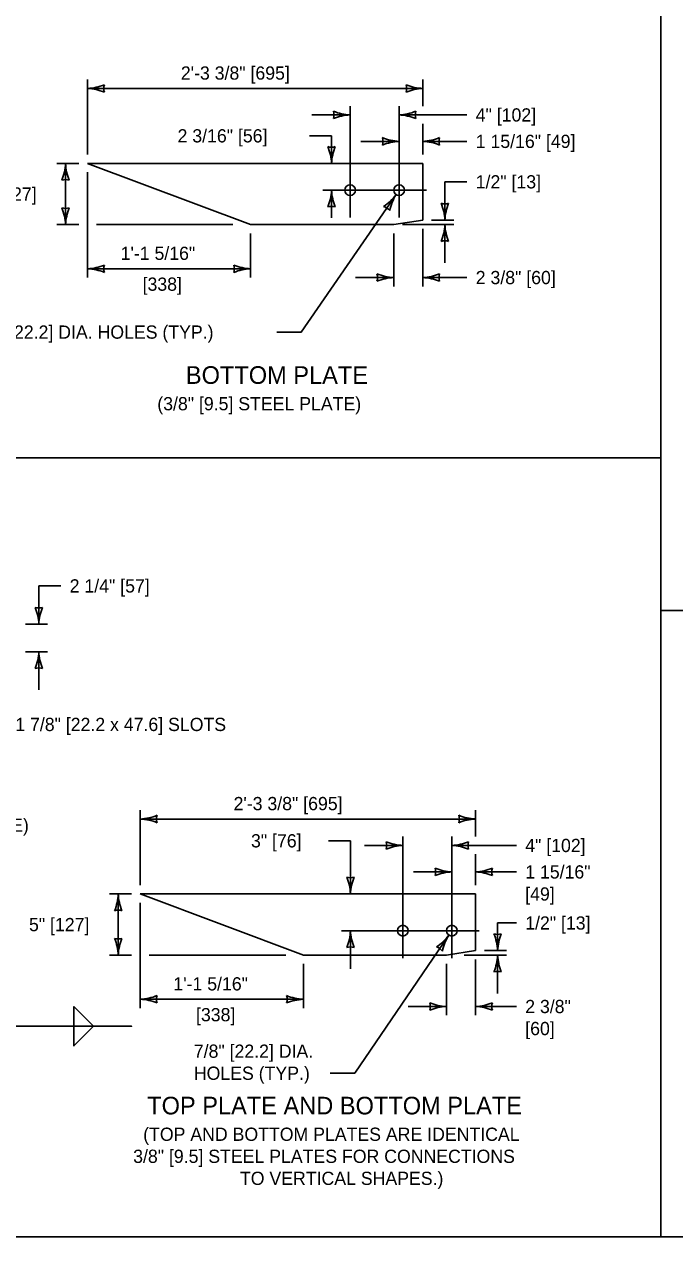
# Model space of a CAD drawing. Extents: x 49991.4 to 50021, y 49987.6 to 50011.4.
# Drawn here: x 50003.04 to 50005.99, y 49987.8 to 49993.3 of the extents above; entities that cross this region are included whole.
import ezdxf

# ---------------------------------------------------------------- set-up
doc = ezdxf.new("R2010")
doc.units = 0
for name, color, linetype in [('Level 1', 7, 'Continuous'), ('Level 2', 7, 'Continuous'), ('Level 3', 7, 'Continuous'), ('Level 5', 7, 'Continuous'), ('Level 7', 7, 'Continuous')]:
    doc.layers.add(name, color=color, linetype=linetype)

msp = doc.modelspace()

# ---------------------------------------------------------------- linework, layer by layer
at = {"layer": 'Level 1'}
for p, q in [((50005.9232, 49998.9992), (50005.9232, 49987.7988)), ((50004.8437, 49992.6677), (50003.3229, 49992.6677)), ((50003.3229, 49992.6677), (50004.0625, 49992.39)), ((50004.8437, 49992.6677), (50004.8437, 49992.4108)), ((50004.7118, 49992.39), (50004.0625, 49992.39)), ((50004.8437, 49992.4108), (50004.7118, 49992.39)), ((50005.9232, 49991.3327), (49999.3835, 49991.3327)), ((50005.9232, 49990.6395), (50016.7501, 49990.6395)), ((50005.083, 49989.3538), (50003.5621, 49989.3538)), ((50003.5621, 49989.3538), (50004.3017, 49989.0761)), ((50005.083, 49989.3538), (50005.083, 49989.0969)), ((50004.951, 49989.0761), (50004.3017, 49989.0761)), ((50005.083, 49989.0969), (50004.951, 49989.0761))]:
    msp.add_line(p, q, dxfattribs=at)
msp.add_lwpolyline([(49999.3835, 49998.9992), (50016.7501, 49998.9992), (50016.7501, 49987.7988), (49999.3835, 49987.7988)], close=True, dxfattribs=at)
for centre in [(50004.5138, 49992.5462), (50004.7361, 49992.5462), (50004.7531, 49989.1872), (50004.9753, 49989.1872)]:
    msp.add_circle(centre, 0.0243, dxfattribs=at)
at = {"layer": 'Level 3'}
for p, q in [((50003.3229, 49992.7077), (50003.3229, 49993.0477)), ((50004.8437, 49992.9277), (50004.8437, 49993.0477)), ((50004.8437, 49993.0077), (50003.3229, 49993.0077)), ((50004.5138, 49992.8877), (50004.3404, 49992.8877)), ((50005.0437, 49992.8877), (50004.7361, 49992.8877)), ((50004.8437, 49992.7077), (50004.8437, 49992.8477)), ((50004.4295, 49992.7929), (50004.3295, 49992.7929)), ((50004.4295, 49992.6677), (50004.4295, 49992.7929)), ((50004.7361, 49992.7677), (50004.5626, 49992.7677)), ((50005.0437, 49992.7677), (50004.8437, 49992.7677)), ((50003.2829, 49992.6677), (50003.1829, 49992.6677)), ((50003.2229, 49992.6677), (50003.2229, 49992.39)), ((50003.3229, 49992.6277), (50003.3229, 49992.15)), ((50004.9437, 49992.4108), (50004.9437, 49992.5842)), ((50004.9437, 49992.5842), (50005.0437, 49992.5842)), ((50004.4295, 49992.5462), (50004.4295, 49992.421)), ((50003.2829, 49992.39), (50003.1829, 49992.39)), ((50003.9825, 49992.39), (50003.3629, 49992.39)), ((50004.7518, 49992.39), (50004.9837, 49992.39)), ((50004.8437, 49992.3708), (50004.8437, 49992.11)), ((50004.8837, 49992.4108), (50004.9837, 49992.4108)), ((50004.9437, 49992.39), (50004.9437, 49992.2165)), ((50004.0625, 49992.35), (50004.0625, 49992.15)), ((50004.7118, 49992.35), (50004.7118, 49992.11)), ((50004.0625, 49992.19), (50003.3229, 49992.19)), ((50004.7118, 49992.15), (50004.5383, 49992.15)), ((50005.0437, 49992.15), (50004.8437, 49992.15)), ((50003.1017, 49990.5778), (50003.1017, 49990.7512)), ((50003.1017, 49990.7512), (50003.2017, 49990.7512)), ((50003.0418, 49990.5778), (50003.1417, 49990.5778)), ((50003.0418, 49990.4528), (50003.1417, 49990.4528)), ((50003.1017, 49990.2794), (50003.1017, 49990.4528)), ((50003.5621, 49989.3938), (50003.5621, 49989.7338)), ((50005.083, 49989.6138), (50005.083, 49989.7338)), ((50005.083, 49989.6938), (50003.5621, 49989.6938)), ((50004.5154, 49989.5949), (50004.4154, 49989.5949)), ((50004.5154, 49989.3538), (50004.5154, 49989.5949)), ((50004.7531, 49989.5738), (50004.5797, 49989.5738)), ((50005.2682, 49989.5738), (50004.9753, 49989.5738)), ((50005.083, 49989.3938), (50005.083, 49989.5338)), ((50004.9753, 49989.4538), (50004.8019, 49989.4538)), ((50005.2682, 49989.4538), (50005.083, 49989.4538)), ((50003.5221, 49989.3538), (50003.4221, 49989.3538)), ((50003.4621, 49989.3538), (50003.4621, 49989.0761)), ((50003.5621, 49989.3138), (50003.5621, 49988.8361)), ((50005.183, 49989.0969), (50005.183, 49989.2221)), ((50005.183, 49989.2221), (50005.2682, 49989.2221)), ((50003.5221, 49989.0761), (50003.4221, 49989.0761)), ((50004.2217, 49989.0761), (50003.6021, 49989.0761)), ((50005.031, 49989.0761), (50005.223, 49989.0761)), ((50005.123, 49989.0969), (50005.223, 49989.0969)), ((50005.183, 49989.0761), (50005.183, 49988.9026)), ((50004.3017, 49989.0361), (50004.3017, 49988.8361)), ((50004.951, 49989.0361), (50004.951, 49988.8033)), ((50005.083, 49989.0569), (50005.083, 49988.8033)), ((50004.3017, 49988.8761), (50003.5621, 49988.8761)), ((50004.951, 49988.8433), (50004.7776, 49988.8433)), ((50005.2682, 49988.8433), (50005.083, 49988.8433))]:
    msp.add_line(p, q, dxfattribs=at)
for points in [[(50004.7223, 49992.5262), (50004.2921, 49991.9026), (50004.181, 49991.9026)], [(50004.9617, 49989.1671), (50004.5349, 49988.5406), (50004.4238, 49988.5406)], [(50003.2609, 49988.7538), (50003.2609, 49988.8429), (50003.35, 49988.7538)], [(50002.6298, 49988.7538), (50003.5221, 49988.7538), (50003.0715, 49988.7538)], [(50003.2609, 49988.7538), (50003.2609, 49988.6646), (50003.35, 49988.7538)]]:
    msp.add_lwpolyline(points, dxfattribs=at)
for centre, radius, start, end in [((50003.3114, 49993.2405), 0.233, 272.8273, 292.0772), ((50003.4511, 49993.0077), 0.0548, 162.1388, 197.8612), ((50004.8529, 49993.2299), 0.2223, 247.456, 267.6395), ((50004.7155, 49993.0077), 0.0548, 342.1388, 17.8612), ((50003.3137, 49992.7856), 0.2223, 67.456, 87.6395), ((50004.8552, 49992.775), 0.233, 92.8273, 112.0772), ((50004.523, 49993.1099), 0.2223, 247.456, 267.6395), ((50004.3856, 49992.8877), 0.0548, 342.1388, 17.8612), ((50004.5253, 49992.655), 0.233, 92.8273, 112.0772), ((50004.7269, 49993.1099), 0.2223, 272.3605, 292.544), ((50004.7246, 49992.655), 0.233, 67.9228, 87.1727), ((50004.8643, 49992.8877), 0.0548, 162.1388, 197.8612), ((50004.7452, 49992.9899), 0.2223, 247.456, 267.6395), ((50004.6079, 49992.7677), 0.0548, 342.1388, 17.8612), ((50004.7476, 49992.535), 0.233, 92.8273, 112.0772), ((50004.8322, 49993.0005), 0.233, 272.8273, 292.0772), ((50004.8345, 49992.5456), 0.2223, 67.456, 87.6395), ((50004.9719, 49992.7677), 0.0548, 162.1388, 197.8612), ((50004.2074, 49992.6586), 0.2223, 2.3605, 22.544), ((50004.4295, 49992.796), 0.0548, 252.1388, 287.8612), ((50004.6623, 49992.6562), 0.233, 157.9228, 177.1727), ((50002.9902, 49992.6792), 0.233, 337.9228, 357.1727), ((50003.445, 49992.6769), 0.2223, 182.3605, 202.544), ((50003.2229, 49992.5395), 0.0548, 72.1388, 107.8612), ((50004.2074, 49992.5554), 0.2223, 337.456, 357.6395), ((50004.6623, 49992.5577), 0.233, 182.8273, 202.0772), ((50004.5437, 49992.6586), 0.2223, 303.2625, 323.446), ((50004.9212, 49992.4049), 0.233, 148.6338, 167.8836), ((50004.7216, 49992.4016), 0.2223, 2.3605, 22.544), ((50004.9437, 49992.539), 0.0548, 252.1388, 287.8612), ((50005.1764, 49992.3993), 0.233, 157.9228, 177.1727), ((50003.0007, 49992.3808), 0.2223, 2.3605, 22.544), ((50003.2229, 49992.5182), 0.0548, 252.1388, 287.8612), ((50003.4556, 49992.3785), 0.233, 157.9228, 177.1727), ((50004.4295, 49992.418), 0.0548, 72.1388, 107.8612), ((50004.6502, 49992.4201), 0.0548, 37.9453, 73.6676), ((50004.7216, 49992.3991), 0.2223, 337.456, 357.6395), ((50005.1764, 49992.4015), 0.233, 182.8273, 202.0772), ((50004.9437, 49992.2617), 0.0548, 72.1388, 107.8612), ((50003.3114, 49992.4227), 0.233, 272.8273, 292.0772), ((50003.4511, 49992.19), 0.0548, 162.1388, 197.8612), ((50004.0716, 49992.4121), 0.2223, 247.456, 267.6395), ((50003.9342, 49992.19), 0.0548, 342.1388, 17.8612), ((50003.3137, 49991.9678), 0.2223, 67.456, 87.6395), ((50004.0739, 49991.9572), 0.233, 92.8273, 112.0772), ((50004.7209, 49992.3721), 0.2223, 247.456, 267.6395), ((50004.5835, 49992.15), 0.0548, 342.1388, 17.8612), ((50004.7232, 49991.9172), 0.233, 92.8273, 112.0772), ((50004.8345, 49992.3721), 0.2223, 272.3605, 292.544), ((50004.8322, 49991.9172), 0.233, 67.9228, 87.1727), ((50004.9719, 49992.15), 0.0548, 162.1388, 197.8612), ((50003.1017, 49990.706), 0.0548, 252.1388, 287.8612), ((50002.869, 49990.5663), 0.233, 2.8273, 22.0772), ((50003.3239, 49990.5686), 0.2223, 157.456, 177.6395), ((50002.869, 49990.4643), 0.233, 337.9228, 357.1727), ((50003.3239, 49990.462), 0.2223, 182.3605, 202.544), ((50003.1017, 49990.3246), 0.0548, 72.1388, 107.8612), ((50003.5506, 49989.9265), 0.233, 272.8273, 292.0772), ((50003.553, 49989.4717), 0.2223, 67.456, 87.6395), ((50003.6903, 49989.6938), 0.0548, 162.1388, 197.8612), ((50005.0921, 49989.916), 0.2223, 247.456, 267.6395), ((50004.9547, 49989.6938), 0.0548, 342.1388, 17.8612), ((50005.0944, 49989.4611), 0.233, 92.8273, 112.0772), ((50004.7623, 49989.796), 0.2223, 247.456, 267.6395), ((50004.6249, 49989.5738), 0.0548, 342.1388, 17.8612), ((50004.7646, 49989.3411), 0.233, 92.8273, 112.0772), ((50004.9662, 49989.796), 0.2223, 272.3605, 292.544), ((50004.9638, 49989.3411), 0.233, 67.9228, 87.1727), ((50005.1035, 49989.5738), 0.0548, 162.1388, 197.8612), ((50004.9845, 49989.676), 0.2223, 247.456, 267.6395), ((50004.8471, 49989.4538), 0.0548, 342.1388, 17.8612), ((50004.9868, 49989.2211), 0.233, 92.8273, 112.0772), ((50005.0715, 49989.6865), 0.233, 272.8273, 292.0772), ((50005.0738, 49989.2317), 0.2223, 67.456, 87.6395), ((50005.2112, 49989.4538), 0.0548, 162.1388, 197.8612), ((50004.2933, 49989.3447), 0.2223, 2.3605, 22.544), ((50004.5154, 49989.482), 0.0548, 252.1388, 287.8612), ((50004.7481, 49989.3423), 0.233, 157.9228, 177.1727), ((50003.2294, 49989.3653), 0.233, 337.9228, 357.1727), ((50003.6843, 49989.363), 0.2223, 182.3605, 202.544), ((50003.4621, 49989.2256), 0.0548, 72.1388, 107.8612), ((50004.2933, 49989.1963), 0.2223, 337.456, 357.6395), ((50004.7481, 49989.1987), 0.233, 182.8273, 202.0772), ((50004.9608, 49989.0877), 0.2223, 2.3605, 22.544), ((50005.183, 49989.2251), 0.0548, 252.1388, 287.8612), ((50005.4157, 49989.0854), 0.233, 157.9228, 177.1727), ((50003.24, 49989.0669), 0.2223, 2.3605, 22.544), ((50003.4621, 49989.2043), 0.0548, 252.1388, 287.8612), ((50003.6948, 49989.0646), 0.233, 157.9228, 177.1727), ((50004.7831, 49989.2995), 0.2223, 303.2625, 323.446), ((50005.1606, 49989.0458), 0.233, 148.6338, 167.8836), ((50004.5154, 49989.059), 0.0548, 72.1388, 107.8612), ((50004.8896, 49989.061), 0.0548, 37.9453, 73.6676), ((50004.9608, 49989.0852), 0.2223, 337.456, 357.6395), ((50005.4157, 49989.0875), 0.233, 182.8273, 202.0772), ((50005.183, 49988.9478), 0.0548, 72.1388, 107.8612), ((50003.5506, 49989.1088), 0.233, 272.8273, 292.0772), ((50003.553, 49988.6539), 0.2223, 67.456, 87.6395), ((50003.6903, 49988.8761), 0.0548, 162.1388, 197.8612), ((50004.3109, 49989.0982), 0.2223, 247.456, 267.6395), ((50004.1735, 49988.8761), 0.0548, 342.1388, 17.8612), ((50004.3132, 49988.6433), 0.233, 92.8273, 112.0772), ((50004.9602, 49989.0655), 0.2223, 247.456, 267.6395), ((50004.8228, 49988.8433), 0.0548, 342.1388, 17.8612), ((50004.9625, 49988.6106), 0.233, 92.8273, 112.0772), ((50005.0738, 49989.0655), 0.2223, 272.3605, 292.544), ((50005.0715, 49988.6106), 0.233, 67.9228, 87.1727), ((50005.2112, 49988.8433), 0.0548, 162.1388, 197.8612)]:
    msp.add_arc(centre, radius, start, end, dxfattribs=at)
at = {"layer": 'Level 5'}
for p, q in [((50004.5138, 49992.9277), (50004.5138, 49992.4219)), ((50004.7361, 49992.9277), (50004.7361, 49992.4219)), ((50004.3895, 49992.5462), (50004.8604, 49992.5462)), ((50004.7531, 49989.6138), (50004.7531, 49989.0629)), ((50004.9753, 49989.6138), (50004.9753, 49989.0629)), ((50004.4754, 49989.1872), (50005.0996, 49989.1872))]:
    msp.add_line(p, q, dxfattribs=at)
at = {"layer": 'Level 7'}
msp.add_line((50004.5154, 49989.1872), (50004.5154, 49989.0137), dxfattribs=at)

# ---------------------------------------------------------------- texts
at = {"layer": 'Level 2'}
for s, p in [('2\'-3 3/8" [695]', (50003.746, 49993.0477)), ('4" [102]', (50005.0837, 49992.8577)), ('2 3/16" [56]', (50003.7311, 49992.7629)), ('1 15/16" [49]', (50005.0837, 49992.7377)), ('1/2" [13]', (50005.0837, 49992.5542)), ('5" [127]', (50002.8179, 49992.4988)), ('1\'-1 5/16"', (50003.4729, 49992.23)), ('[338]', (50003.5724, 49992.09)), ('2 3/8" [60]', (50005.0837, 49992.12)), ('7/8" [22.2] DIA. HOLES (TYP.)', (50002.8044, 49991.8726)), ('(3/8" [9.5] STEEL PLATE)', (50003.6391, 49991.5477)), ('2 1/4" [57]', (50003.2417, 49990.7212)), ('7/8" x 1 7/8" [22.2 x 47.6] SLOTS', (50002.7702, 49990.0928)), ('2\'-3 3/8" [695]', (50003.9852, 49989.7338)), ('(3/8" [9.5] STEEL PLATE)', (50002.1315, 49989.6358)), ('3" [76]', (50004.0643, 49989.5649)), ('4" [102]', (50005.3082, 49989.5438)), ('1 15/16" ', (50005.3082, 49989.4238)), ('[49]', (50005.3082, 49989.3238)), ('5" [127]', (50003.0572, 49989.1849)), ('1/2" [13]', (50005.3082, 49989.1921)), ('1\'-1 5/16"', (50003.7121, 49988.9161)), ('2 3/8" ', (50005.3082, 49988.8133)), ('[338]', (50003.8148, 49988.7761)), ('[60]', (50005.3082, 49988.7133)), ('7/8" [22.2] DIA. ', (50003.8049, 49988.6106)), ('HOLES (TYP.)', (50003.8049, 49988.5106)), ('(TOP AND BOTTOM PLATES ARE IDENTICAL', (50003.5751, 49988.2338)), ('3/8" [9.5] STEEL PLATES FOR CONNECTIONS ', (50003.5297, 49988.1338)), ('TO VERTICAL SHAPES.)', (50004.0141, 49988.0338))]:
    msp.add_text(s, height=0.06, rotation=360, dxfattribs=at).set_placement(p)
for s, p in [('BOTTOM PLATE', (50003.7688, 49991.6677)), ('TOP PLATE AND BOTTOM PLATE', (50003.5934, 49988.3538))]:
    msp.add_text(s, height=0.08, dxfattribs=at).set_placement(p)

doc.saveas('drawing.dxf')
